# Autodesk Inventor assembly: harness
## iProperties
HarnessSettings: <HarnessSettings><Defaults><Segments><Diameter value="0.200 in" fromwires="True"/><Offset value="0.100 in"/><ColorStyle value="Blue"/><BendRadius value="19" fro
Control State: 0
Master: False
Checked Out: False
Part Number: harness
Document SubType Name: Assembly
Created: 2002-07
Designer: invbi
Shininess: 64.0
Length Units: 11272
Angle Units: 11279
Time Units: 11290
Mass Units: 11286
Length Display Precision: 3
Angle Display Precision: 2
Compacted: True
Density: 0.0
Volumn: 0.0
Area: 0.0
PropertySet Name: Model Information
HarnessSettings: <HarnessSettings><Defaults><Segments><Diameter value="0.200 in" fromwires="True"/><Offset value="0.100 in"/><ColorStyle value="Blue"/><RoundUp value=""/><BendRa
Author: invbi
